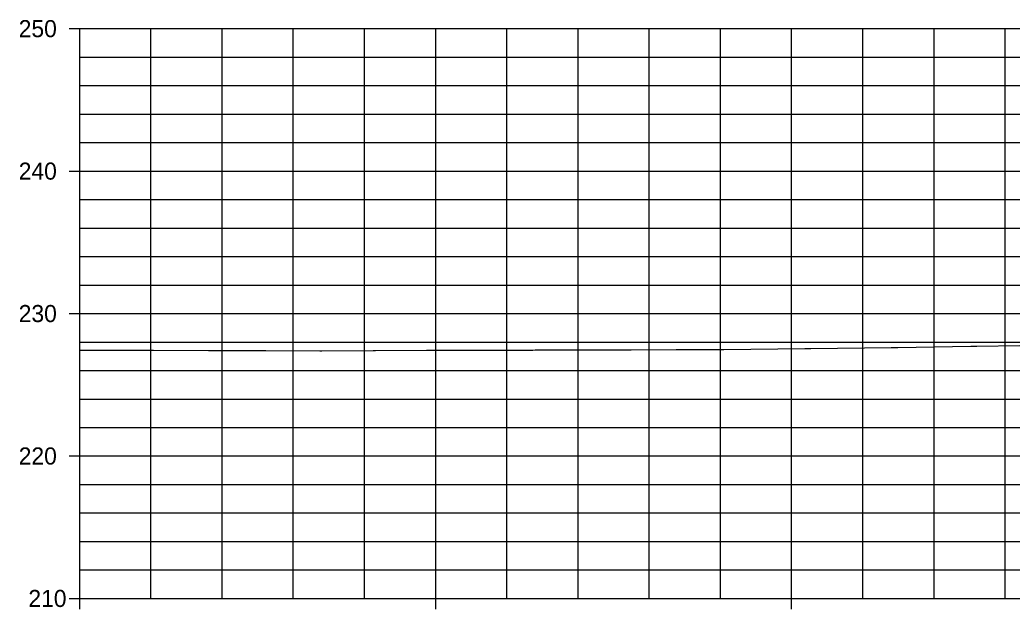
# Model space of a CAD drawing. Extents: x 1801553 to 1803097, y 521610 to 523048.
# Drawn here: x 1801757.8 to 1802036.6, y 522338.5 to 522503.9 of the extents above; entities that cross this region are included whole.
import ezdxf

# ---------------------------------------------------------------- set-up
doc = ezdxf.new("R2010")
doc.units = 0
for name, color, linetype in [('R_Axis', 7, 'Continuous'), ('R_Axis Annot', 7, 'Continuous'), ('R_Exist Surface', 7, 'Continuous'), ('R_Grid', 7, 'Continuous')]:
    doc.layers.add(name, color=color, linetype=linetype)

msp = doc.modelspace()

# ---------------------------------------------------------------- linework, layer by layer
at = {"layer": 'R_Axis'}
for q in [(1801774.68, 522501.48), (1802774.68, 522341.48)]:
    msp.add_line((1801774.68, 522341.48), q, dxfattribs=at)
at = {"layer": 'R_Exist Surface'}
msp.add_lwpolyline([(1801774.68, 522411.19), (1801779.53, 522411.19), (1801779.55, 522411.19), (1801795.04, 522411.15), (1801795.2, 522411.15), (1801795.36, 522411.15), (1801810.85, 522411.12), (1801811.16, 522411.12), (1801826.5, 522411.09), (1801826.96, 522411.08), (1801842.14, 522411.05), (1801842.73, 522411.05), (1801857.1, 522411.1), (1801857.73, 522411.1), (1801872.07, 522411.15), (1801872.73, 522411.15), (1801887.03, 522411.2), (1801887.73, 522411.2), (1801902, 522411.24), (1801902.65, 522411.25), (1801915.41, 522411.29), (1801916.11, 522411.29), (1801928.83, 522411.33), (1801929.57, 522411.33), (1801942.24, 522411.37), (1801954.83, 522411.41), (1801955.65, 522411.42), (1801978.39, 522411.69), (1801980.11, 522411.7), (1802002.64, 522411.97), (1802004.56, 522411.99), (1802025.05, 522412.3), (1802026.71, 522412.32), (1802038.77, 522412.55)], dxfattribs=at)
at = {"layer": 'R_Grid'}
for p, q in [((1801771.68, 522501.48), (1801774.68, 522501.48)), ((1801771.68, 522501.48), (1801774.68, 522501.48)), ((1801774.68, 522501.48), (1802774.68, 522501.48)), ((1801774.68, 522501.48), (1802774.68, 522501.48)), ((1801794.68, 522341.48), (1801794.68, 522501.48)), ((1801814.68, 522341.48), (1801814.68, 522501.48)), ((1801834.68, 522341.48), (1801834.68, 522501.48)), ((1801854.68, 522341.48), (1801854.68, 522501.48)), ((1801874.68, 522341.48), (1801874.68, 522501.48)), ((1801894.68, 522341.48), (1801894.68, 522501.48)), ((1801914.68, 522341.48), (1801914.68, 522501.48)), ((1801934.68, 522341.48), (1801934.68, 522501.48)), ((1801954.68, 522341.48), (1801954.68, 522501.48)), ((1801974.68, 522341.48), (1801974.68, 522501.48)), ((1801994.68, 522341.48), (1801994.68, 522501.48)), ((1802014.68, 522341.48), (1802014.68, 522501.48)), ((1802034.68, 522341.48), (1802034.68, 522501.48)), ((1801774.68, 522493.48), (1801776.18, 522493.48)), ((1801774.68, 522493.48), (1802774.68, 522493.48)), ((1801774.68, 522485.48), (1801776.18, 522485.48)), ((1801774.68, 522485.48), (1802774.68, 522485.48)), ((1801774.68, 522477.48), (1801776.18, 522477.48)), ((1801774.68, 522477.48), (1802774.68, 522477.48)), ((1801774.68, 522469.48), (1801776.18, 522469.48)), ((1801774.68, 522469.48), (1802774.68, 522469.48)), ((1801771.68, 522461.48), (1801774.68, 522461.48)), ((1801774.68, 522461.48), (1802774.68, 522461.48)), ((1801774.68, 522453.48), (1801776.18, 522453.48)), ((1801774.68, 522453.48), (1802774.68, 522453.48)), ((1801774.68, 522445.48), (1801776.18, 522445.48)), ((1801774.68, 522445.48), (1802774.68, 522445.48)), ((1801774.68, 522437.48), (1801776.18, 522437.48)), ((1801774.68, 522437.48), (1802774.68, 522437.48)), ((1801774.68, 522429.48), (1801776.18, 522429.48)), ((1801774.68, 522429.48), (1802774.68, 522429.48)), ((1801771.68, 522421.48), (1801774.68, 522421.48)), ((1801774.68, 522421.48), (1802774.68, 522421.48)), ((1801774.68, 522413.48), (1801776.18, 522413.48)), ((1801774.68, 522413.48), (1802774.68, 522413.48)), ((1801774.68, 522405.48), (1801776.18, 522405.48)), ((1801774.68, 522405.48), (1802774.68, 522405.48)), ((1801774.68, 522397.48), (1801776.18, 522397.48)), ((1801774.68, 522397.48), (1802774.68, 522397.48)), ((1801774.68, 522389.48), (1801776.18, 522389.48)), ((1801774.68, 522389.48), (1802774.68, 522389.48)), ((1801771.68, 522381.48), (1801774.68, 522381.48)), ((1801774.68, 522381.48), (1802774.68, 522381.48)), ((1801774.68, 522373.48), (1801776.18, 522373.48)), ((1801774.68, 522373.48), (1802774.68, 522373.48)), ((1801774.68, 522365.48), (1801776.18, 522365.48)), ((1801774.68, 522365.48), (1802774.68, 522365.48)), ((1801774.68, 522357.48), (1801776.18, 522357.48)), ((1801774.68, 522357.48), (1802774.68, 522357.48)), ((1801774.68, 522349.48), (1801776.18, 522349.48)), ((1801774.68, 522349.48), (1802774.68, 522349.48)), ((1801771.68, 522341.48), (1801774.68, 522341.48)), ((1801774.68, 522338.48), (1801774.68, 522341.48)), ((1801874.68, 522338.48), (1801874.68, 522341.48)), ((1801974.68, 522338.48), (1801974.68, 522341.48))]:
    msp.add_line(p, q, dxfattribs=at)

# ---------------------------------------------------------------- texts
at = {"layer": 'R_Axis Annot'}
for s, height, p in [('250', 4.8, (1801757.53, 522499.08)), ('240', 4.8, (1801757.53, 522459.08)), ('230', 4.8, (1801757.53, 522419.08)), ('220', 4.8, (1801757.53, 522379.08)), ('210', 4.8, (1801760.25, 522339.08)), ('-', 0.0001, (1801774.68, 522341.48))]:
    msp.add_text(s, height=height, dxfattribs=at).set_placement(p)

doc.saveas('drawing.dxf')
